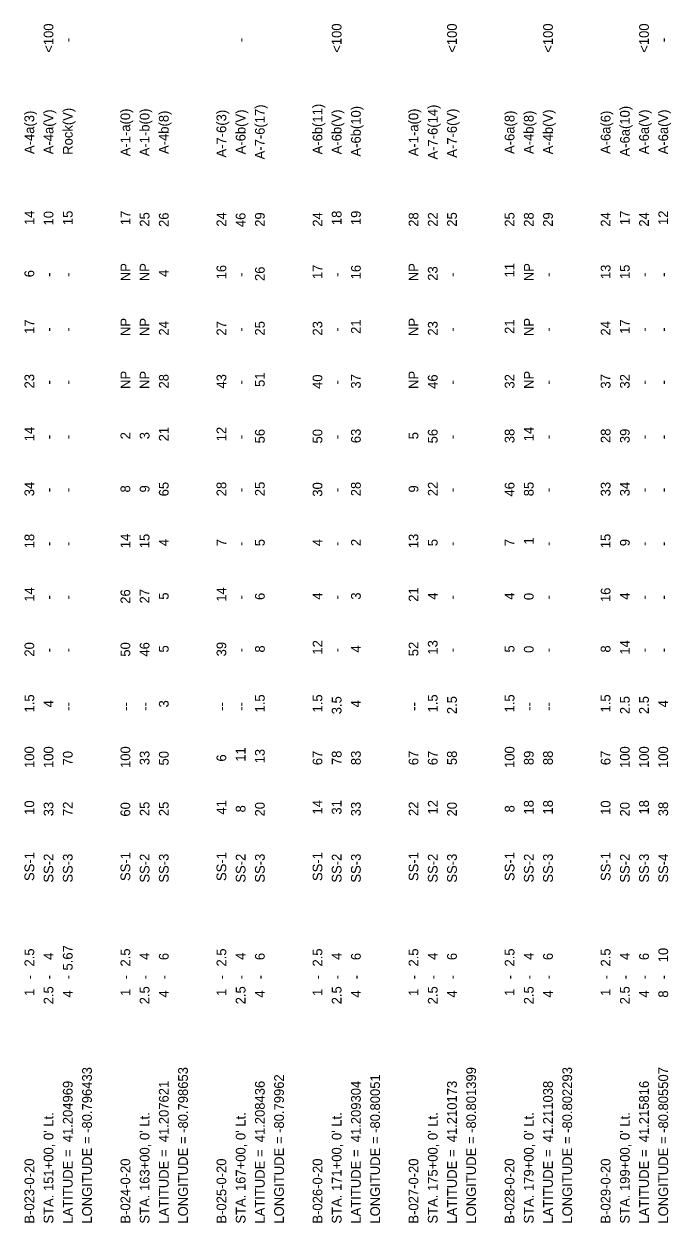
# Model space of a CAD drawing. Extents: x 0 to 83.4, y 4.5 to 46.4.
# Drawn here: x 58.19 to 67.51, y 4.53 to 21.78 of the extents above; entities that cross this region are included whole.
import ezdxf

# ---------------------------------------------------------------- set-up
doc = ezdxf.new("R2010")
doc.units = 0
doc.layers.add('TX_P_1', color=7, linetype='Continuous')

msp = doc.modelspace()

# ---------------------------------------------------------------- texts
at = {"layer": 'TX_P_1'}
for s, p in [('<100', (58.61, 21.37)), ('<100', (62.76, 21.37)), ('<100', (64.421, 21.37)), ('<100', (65.804, 21.37)), ('<100', (67.187, 21.37)), ('-', (58.887, 21.522)), ('-', (61.377, 21.522)), ('-', (67.464, 21.522)), ('A-4a(V)', (58.61, 19.909)), ('Rock(V)', (58.887, 19.901)), ('A-1-a(0)', (59.717, 19.88)), ('A-1-b(0)', (59.994, 19.88)), ('A-6b(V)', (61.377, 19.908)), ('A-7-6(17)', (61.654, 19.835)), ('A-6b(11)', (62.484, 19.907)), ('A-6b(V)', (62.76, 19.908)), ('A-6b(10)', (63.037, 19.876)), ('A-1-a(0)', (63.867, 19.88)), ('A-7-6(14)', (64.144, 19.833)), ('A-7-6(V)', (64.421, 19.859)), ('A-4b(V)', (65.804, 19.908)), ('A-6a(10)', (66.911, 19.877)), ('A-6a(V)', (67.187, 19.908)), ('A-6a(V)', (67.464, 19.908)), ('A-4a(3)', (58.334, 19.912)), ('A-4b(8)', (60.27, 19.913)), ('A-7-6(3)', (61.1, 19.862)), ('A-6a(8)', (65.251, 19.913)), ('A-4b(8)', (65.527, 19.913)), ('A-6a(6)', (66.634, 19.912)), ('14', (58.334, 18.89)), ('10', (58.61, 18.884)), ('15', (58.887, 18.889)), ('17', (59.717, 18.889)), ('25', (59.994, 18.866)), ('26', (60.27, 18.862)), ('24', (61.1, 18.866)), ('46', (61.377, 18.86)), ('29', (61.654, 18.865)), ('24', (62.484, 18.866)), ('18', (62.76, 18.889)), ('19', (63.037, 18.889)), ('28', (63.867, 18.865)), ('22', (64.144, 18.866)), ('25', (64.421, 18.866)), ('25', (65.251, 18.866)), ('28', (65.527, 18.865)), ('29', (65.804, 18.865)), ('24', (66.634, 18.866)), ('17', (66.911, 18.889)), ('24', (67.187, 18.866)), ('12', (67.464, 18.89)), ('NP', (59.717, 18.082)), ('NP', (59.994, 18.082)), ('16', (61.1, 18.108)), ('17', (62.484, 18.112)), ('16', (63.037, 18.108)), ('NP', (63.867, 18.082)), ('11', (65.251, 18.136)), ('NP', (65.527, 18.082)), ('13', (66.634, 18.112)), ('15', (66.911, 18.112)), ('6', (58.334, 18.138)), ('-', (58.61, 18.145)), ('-', (58.887, 18.145)), ('4', (60.27, 18.142)), ('-', (61.377, 18.145)), ('26', (61.654, 18.084)), ('-', (62.76, 18.145)), ('23', (64.144, 18.088)), ('-', (64.421, 18.145)), ('-', (65.804, 18.145)), ('-', (67.187, 18.145)), ('-', (67.464, 18.145)), ('17', (58.334, 17.323)), ('NP', (59.717, 17.293)), ('NP', (59.994, 17.293)), ('24', (60.27, 17.299)), ('27', (61.1, 17.299)), ('25', (61.654, 17.299)), ('23', (62.484, 17.299)), ('21', (63.037, 17.323)), ('NP', (63.867, 17.293)), ('23', (64.144, 17.299)), ('21', (65.251, 17.323)), ('NP', (65.527, 17.293)), ('24', (66.634, 17.299)), ('17', (66.911, 17.323)), ('-', (58.61, 17.356)), ('-', (58.887, 17.356)), ('-', (61.377, 17.356)), ('-', (62.76, 17.356)), ('-', (64.421, 17.356)), ('-', (65.804, 17.356)), ('-', (67.187, 17.356)), ('-', (67.464, 17.356)), ('NP', (59.717, 16.531)), ('NP', (59.994, 16.531)), ('51', (61.654, 16.56)), ('NP', (63.867, 16.531)), ('NP', (65.527, 16.531)), ('23', (58.334, 16.538)), ('-', (58.61, 16.595)), ('-', (58.887, 16.595)), ('28', (60.27, 16.537)), ('43', (61.1, 16.536)), ('-', (61.377, 16.595)), ('40', (62.484, 16.531)), ('-', (62.76, 16.595)), ('37', (63.037, 16.536)), ('46', (64.144, 16.532)), ('-', (64.421, 16.595)), ('32', (65.251, 16.536)), ('-', (65.804, 16.595)), ('37', (66.634, 16.536)), ('32', (66.911, 16.536)), ('-', (67.187, 16.595)), ('-', (67.464, 16.595)), ('14', (58.334, 15.777)), ('2', (59.717, 15.806)), ('3', (59.994, 15.806)), ('21', (60.27, 15.776)), ('12', (61.1, 15.777)), ('56', (61.654, 15.747)), ('50', (62.484, 15.746)), ('63', (63.037, 15.75)), ('5', (63.867, 15.806)), ('56', (64.144, 15.747)), ('38', (65.251, 15.75)), ('14', (65.527, 15.777)), ('28', (66.634, 15.752)), ('39', (66.911, 15.75)), ('-', (58.61, 15.809)), ('-', (58.887, 15.809)), ('-', (61.377, 15.809)), ('-', (62.76, 15.809)), ('-', (64.421, 15.809)), ('-', (65.804, 15.809)), ('-', (67.187, 15.809)), ('-', (67.464, 15.809)), ('34', (58.334, 14.986)), ('34', (66.911, 14.986)), ('-', (58.61, 15.044)), ('-', (58.887, 15.044)), ('8', (59.717, 15.04)), ('9', (59.994, 15.04)), ('65', (60.27, 14.985)), ('28', (61.1, 14.986)), ('-', (61.377, 15.044)), ('25', (61.654, 14.987)), ('30', (62.484, 14.98)), ('-', (62.76, 15.044)), ('28', (63.037, 14.986)), ('9', (63.867, 15.04)), ('22', (64.144, 14.987)), ('-', (64.421, 15.044)), ('46', (65.251, 14.982)), ('85', (65.527, 14.986)), ('-', (65.804, 15.044)), ('33', (66.634, 14.985)), ('-', (67.187, 15.044)), ('-', (67.464, 15.044)), ('18', (58.334, 14.237)), ('14', (59.717, 14.238)), ('15', (59.994, 14.238)), ('4', (60.27, 14.268)), ('7', (61.1, 14.267)), ('5', (61.654, 14.267)), ('4', (62.484, 14.268)), ('2', (63.037, 14.268)), ('13', (63.867, 14.238)), ('5', (64.144, 14.267)), ('7', (65.251, 14.267)), ('1', (65.527, 14.291)), ('15', (66.634, 14.238)), ('9', (66.911, 14.267)), ('-', (58.61, 14.271)), ('-', (58.887, 14.271)), ('-', (61.377, 14.271)), ('-', (62.76, 14.271)), ('-', (64.421, 14.271)), ('-', (65.804, 14.271)), ('-', (67.187, 14.271)), ('-', (67.464, 14.271)), ('14', (58.334, 13.468)), ('26', (59.717, 13.439)), ('27', (59.994, 13.443)), ('14', (61.1, 13.468)), ('21', (63.867, 13.467)), ('16', (66.634, 13.463)), ('-', (58.61, 13.5)), ('-', (58.887, 13.5)), ('5', (60.27, 13.497)), ('-', (61.377, 13.5)), ('6', (61.654, 13.493)), ('4', (62.484, 13.497)), ('-', (62.76, 13.5)), ('3', (63.037, 13.497)), ('4', (64.144, 13.497)), ('-', (64.421, 13.5)), ('4', (65.251, 13.497)), ('0', (65.527, 13.491)), ('-', (65.804, 13.5)), ('4', (66.911, 13.497)), ('-', (67.187, 13.5)), ('-', (67.464, 13.5)), ('20', (58.334, 12.678)), ('-', (58.61, 12.74)), ('-', (58.887, 12.74)), ('50', (59.717, 12.677)), ('46', (59.994, 12.678)), ('5', (60.27, 12.737)), ('39', (61.1, 12.681)), ('-', (61.377, 12.74)), ('8', (61.654, 12.736)), ('12', (62.484, 12.707)), ('-', (62.76, 12.74)), ('4', (63.037, 12.737)), ('52', (63.867, 12.683)), ('13', (64.144, 12.707)), ('-', (64.421, 12.74)), ('5', (65.251, 12.737)), ('0', (65.527, 12.731)), ('-', (65.804, 12.74)), ('8', (66.634, 12.736)), ('14', (66.911, 12.707)), ('-', (67.187, 12.74)), ('-', (67.464, 12.74)), ('1.5', (58.334, 11.874)), ('1.5', (61.654, 11.874)), ('1.5', (62.484, 11.874)), ('3.5', (62.76, 11.848)), ('1.5', (64.144, 11.874)), ('2.5', (64.421, 11.85)), ('1.5', (65.251, 11.874)), ('1.5', (66.634, 11.874)), ('2.5', (66.911, 11.85)), ('2.5', (67.187, 11.85)), ('4', (58.61, 11.947)), ('--', (58.887, 11.898)), ('--', (59.717, 11.898)), ('--', (59.994, 11.898)), ('3', (60.27, 11.946)), ('--', (61.1, 11.898)), ('--', (61.377, 11.898)), ('4', (63.037, 11.947)), ('--', (63.867, 11.898)), ('--', (65.527, 11.898)), ('--', (65.804, 11.898)), ('4', (67.464, 11.947)), ('100', (58.334, 11.075)), ('100', (58.61, 11.075)), ('70', (58.887, 11.112)), ('100', (59.717, 11.075)), ('33', (59.994, 11.115)), ('50', (60.27, 11.111)), ('6', (61.1, 11.167)), ('11', (61.377, 11.165)), ('13', (61.654, 11.141)), ('67', (62.484, 11.115)), ('78', (62.76, 11.117)), ('83', (63.037, 11.116)), ('67', (63.867, 11.115)), ('67', (64.144, 11.115)), ('58', (64.421, 11.116)), ('100', (65.251, 11.075)), ('89', (65.527, 11.116)), ('88', (65.804, 11.116)), ('67', (66.634, 11.115)), ('100', (66.911, 11.075)), ('100', (67.187, 11.075)), ('100', (67.464, 11.075)), ('10', (58.334, 10.4)), ('33', (58.61, 10.38)), ('72', (58.887, 10.383)), ('60', (59.717, 10.375)), ('25', (59.994, 10.382)), ('25', (60.27, 10.382)), ('41', (61.1, 10.404)), ('8', (61.377, 10.435)), ('20', (61.654, 10.377)), ('14', (62.484, 10.406)), ('31', (62.76, 10.404)), ('33', (63.037, 10.38)), ('22', (63.867, 10.383)), ('12', (64.144, 10.406)), ('20', (64.421, 10.377)), ('8', (65.251, 10.435)), ('18', (65.527, 10.405)), ('18', (65.804, 10.405)), ('10', (66.634, 10.4)), ('20', (66.911, 10.377)), ('18', (67.187, 10.405)), ('38', (67.464, 10.38)), ('SS-1', (58.334, 9.448)), ('SS-1', (59.717, 9.448)), ('SS-1', (61.1, 9.448)), ('SS-1', (62.484, 9.448)), ('SS-1', (63.867, 9.448)), ('SS-1', (65.251, 9.448)), ('SS-1', (66.634, 9.448)), ('SS-2', (58.61, 9.425)), ('SS-3', (58.887, 9.425)), ('SS-2', (59.994, 9.425)), ('SS-3', (60.27, 9.425)), ('SS-2', (61.377, 9.425)), ('SS-3', (61.654, 9.425)), ('SS-2', (62.76, 9.425)), ('SS-3', (63.037, 9.425)), ('SS-2', (64.144, 9.425)), ('SS-3', (64.421, 9.425)), ('SS-2', (65.527, 9.425)), ('SS-3', (65.804, 9.425)), ('SS-2', (66.911, 9.425)), ('SS-3', (67.187, 9.425)), ('SS-4', (67.464, 9.425)), ('2.5', (58.334, 8.217)), ('5.67', (58.887, 8.16)), ('2.5', (59.717, 8.217)), ('2.5', (61.1, 8.217)), ('2.5', (62.484, 8.217)), ('2.5', (63.867, 8.217)), ('2.5', (65.251, 8.217)), ('2.5', (66.634, 8.217)), ('10', (67.464, 8.278)), ('4', (58.61, 8.313)), ('4', (59.994, 8.313)), ('6', (60.27, 8.309)), ('4', (61.377, 8.313)), ('6', (61.654, 8.309)), ('4', (62.76, 8.313)), ('6', (63.037, 8.309)), ('4', (64.144, 8.313)), ('6', (64.421, 8.309)), ('4', (65.527, 8.313)), ('6', (65.804, 8.309)), ('4', (66.911, 8.313)), ('6', (67.187, 8.309)), ('-', (58.334, 8.033)), ('-', (58.61, 8.033)), ('-', (58.887, 8.033)), ('-', (59.717, 8.033)), ('-', (59.994, 8.033)), ('-', (60.27, 8.033)), ('-', (61.1, 8.033)), ('-', (61.377, 8.033)), ('-', (61.654, 8.033)), ('-', (62.484, 8.033)), ('-', (62.76, 8.033)), ('-', (63.037, 8.033)), ('-', (63.867, 8.033)), ('-', (64.144, 8.033)), ('-', (64.421, 8.033)), ('-', (65.251, 8.033)), ('-', (65.527, 8.033)), ('-', (65.804, 8.033)), ('-', (66.634, 8.033)), ('-', (66.911, 8.033)), ('-', (67.187, 8.033)), ('-', (67.464, 8.033)), ('1', (58.334, 7.793)), ('2.5', (58.61, 7.673)), ('4', (58.887, 7.77)), ('1', (59.717, 7.793)), ('2.5', (59.994, 7.673)), ('4', (60.27, 7.77)), ('1', (61.1, 7.793)), ('2.5', (61.377, 7.673)), ('4', (61.654, 7.77)), ('1', (62.484, 7.793)), ('2.5', (62.76, 7.673)), ('4', (63.037, 7.77)), ('1', (63.867, 7.793)), ('2.5', (64.144, 7.673)), ('4', (64.421, 7.77)), ('1', (65.251, 7.793)), ('2.5', (65.527, 7.673)), ('4', (65.804, 7.77)), ('1', (66.634, 7.793)), ('2.5', (66.911, 7.673)), ('4', (67.187, 7.77)), ('8', (67.464, 7.769)), ('LONGITUDE = -80.796433', (59.164, 4.517)), ('LONGITUDE = -80.798653', (60.547, 4.517)), ('LONGITUDE = -80.801399', (64.697, 4.517)), ('LONGITUDE = -80.802293', (66.081, 4.517)), ('LONGITUDE = -80.805507', (67.464, 4.517)), ('LATITUDE =  41.204969', (58.887, 4.517)), ('LATITUDE =  41.207621', (60.27, 4.517)), ('LATITUDE =  41.208436', (61.654, 4.517)), ('LONGITUDE = -80.79962', (61.93, 4.517)), ('LATITUDE =  41.209304', (63.037, 4.517)), ('LONGITUDE = -80.80051', (63.314, 4.517)), ('LATITUDE =  41.210173', (64.421, 4.517)), ('LATITUDE =  41.211038', (65.804, 4.517)), ('LATITUDE =  41.215816', (67.187, 4.517)), ("STA. 151+00, 0' Lt.", (58.61, 4.517)), ("STA. 163+00, 0' Lt.", (59.994, 4.517)), ("STA. 167+00, 0' Lt.", (61.377, 4.517)), ("STA. 171+00, 0' Lt.", (62.76, 4.517)), ("STA. 175+00, 0' Lt.", (64.144, 4.517)), ("STA. 179+00, 0' Lt.", (65.527, 4.517)), ("STA. 199+00, 0' Lt.", (66.911, 4.517)), ('B-023-0-20', (58.334, 4.517)), ('B-024-0-20', (59.717, 4.517)), ('B-025-0-20', (61.1, 4.517)), ('B-026-0-20', (62.484, 4.517)), ('B-027-0-20', (63.867, 4.517)), ('B-028-0-20', (65.251, 4.517)), ('B-029-0-20', (66.634, 4.517))]:
    msp.add_text(s, height=0.14, rotation=90, dxfattribs=at).set_placement(p)

doc.saveas('drawing.dxf')
